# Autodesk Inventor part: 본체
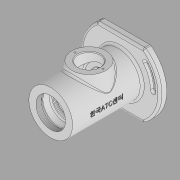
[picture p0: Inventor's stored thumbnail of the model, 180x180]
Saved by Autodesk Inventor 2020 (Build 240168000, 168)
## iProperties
Created: 2022-05
Part Number: 본체
Material: 일반
Document SubType Name: Modeling
Designer: User
Density: 1 g/cm^3
Appearance: 기본값
Mass: 256.279 g
Surface Area: 622.612 cm^2
Volume: 256.279 cm^3
Author: User
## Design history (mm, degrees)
sketch "스케치1"
  geometry: L1 (57.5, 0)-(-57.5, 0); L2 (-57.5, 0)-(-57.5, 32); L3 (44.5, 32)-(44.5, 58); L4 (44.5, 58)-(54.5, 58); L5 (54.5, 58)-(54.5, 36); L6 (54.5, 36)-(57.5, 36); L7 (57.5, 36)-(57.5, 0); L8 (-49.5, 0)-(-49.5, 24); L9 (-49.5, 24)-(-46.5, 24); L10 (-46.5, 24)-(-46.5, 22.5); L11 (-46.5, 22.5)-(-35.5, 22.5); L12 (-35.5, 22.5)-(-35.5, 17.5); L13 (-35.5, 17.5)-(-33.25, 17.5); L14 (-33.25, 17.5)-(-33.25, 18.5); L15 (-33.25, 18.5)-(-31.5, 18.5); L16 (-31.5, 18.5)-(-31.5, 17.5); L17 (-31.5, 17.5)-(-20.5, 17.5); L18 (-20.5, 17.5)-(-20.5, 27); L19 (-20.5, 27)-(17.5, 27); L20 (17.5, 27)-(17.5, 17.5); L21 (17.5, 17.5)-(28.5, 17.5); L22 (28.5, 17.5)-(28.5, 15); L23 (28.5, 15)-(33.5, 15); L24 (33.5, 15)-(33.5, 11); L25 (33.5, 11)-(36.2, 11); L26 (36.2, 11)-(36.2, 15); L27 (36.2, 15)-(43.5, 15); L28 (-57.5, 32)-(44.5, 32); L29 (43.5, 15)-(43.5, 20); L30 (43.5, 20)-(57.5, 30); 2 further points
  constraints: 60 end point, 20 perpendicular, 6 point on line, 3 vertical, 2 coincident, 2 horizontal, 1 midpoint
  dimensions: "d1" = 115 distance between parallel lines of L7 L2; "d2" = 13 distance between parallel lines of L7 L3; "d4" = 3 distance between parallel lines of L7 L5; "d5" = 116 diameter of L4 L1; "d6" = 72 diameter of L6 L1; "d7" = 64 diameter of L28 L1; "d8" = 48 diameter of L9 L1; "d9" = 45 diameter of L11 L1; "d10" = 8 distance between parallel lines of L2 L8; "d11" = 3 distance of L8.end L9.end; "d13" = 22 distance between parallel lines of L2 L12; "d14" = 14 horizontal distance of L27.end L30.end; "d17" = 29 distance between parallel lines of L22 L7; "d18" = 11 distance of L20.end L21.end; "d19" = 38 distance of L18.end L19.end; "d20" = 11 distance of L16.end L17.end; "d21" = 5 distance of L22.end L23.end; "d22" = 35 diameter of L13 L1; "d23" = 54 diameter of L19 L1; "d24" = 30 diameter of L23 L1; "d25" = 22 diameter of L25 L1; "d28" = 1.75 distance of L14.end L15.end; "d29" = 37 diameter of L15 L1; "d74" = 60 diameter of L30.end L1; "d75" = 20 vertical distance of L1.start L29.end; "d76" = 7.3 distance of L26.end L27.end; "d77" = 30 diameter of L27 L1
revolve "회전1" sketch "스케치1" stored, may be unused: angle "d30" = 90 deg
sketch "스케치2"
  geometry: C1 r 32 at (0, 0) reference; 2 further points
  constraints: 1 coincident
hole "구멍1" sketch "스케치2" at (0, 0) diameter "d31" = 43.376; stored, may be unused: countersink angle "d35" = 90 deg, drill point angle "d37" = 0 deg; dims "d32" = 8, "d33" = 4, "d34" = 2, "d36" = 8
sketch "스케치3"
  geometry: L1 (-47, -60)-(47, -60); L2 (47, -60)-(47, 60); L3 (47, 60)-(-47, 60); L4 (-47, 60)-(-47, -60); L5 (-47, -60)-(47, 60); L6 (47, -60)-(-47, 60); C1 r 58 at (0, 0) reference; 5 further points
  constraints: 12 end point, 2 midpoint, 2 parallel, 1 horizontal, 1 perpendicular
  dimensions: "d40" = 94 distance of L3.end L2.end; "d41" = 120 distance of L2.end L1.end
extrude "돌출1" cut sketch "스케치3" distance "d42" = 10; taper "d43" = 0 deg
sketch "스케치4"
  geometry: L1 (-47, 33.985)-(-47, 81.985); L2 (-47, 33.985)-(-77.854, 70.755); C1 r 32 at (-47, 33.985) reference; A1 r 48 centre (-47, 33.985) between (-47, 81.985) and (-77.854, 70.755); A2 r 4 centre (-77.854, 70.755) between (-80.425, 73.82) and (-78.806, 66.87); A3 r 4 centre (-47, 81.985) between (-47, 77.985) and (-47, 85.985); A4 r 44 centre (-47, 33.985) between (-47, 77.985) and (-75.283, 67.691); A5 r 52 centre (-47, 33.985) between (-47, 85.985) and (-80.425, 73.82); A6 r 45.75 centre (-47, 33.985) between (-47, 79.735) and (-78.806, 66.87); A7 r 50.25 centre (-47, 33.985) between (-47, 84.235) and (-81.818, 70.218); A8 r 2.25 centre (-47, 81.985) between (-47, 79.735) and (-47, 84.235); 4 further points
  constraints: 17 point on circle, 8 centre point, 6 coincident, 4 end point, 3 point on line, 1 tangent, 1 vertical
  dimensions: "d44" = 96 diameter of A1; "d45" = 40 deg angle of L2 L1; "d46" = 8 diameter of A2; "d47" = 8 diameter of A3; "d48" = 2.25 radial gap between concentric circles of A1 A6; "d49" = 2.25 radial gap between concentric circles of A1 A7
extrude "돌출2" cut sketch "스케치4" extent not by distance; stored distance "d50" = 0; taper "d51" = 0 deg
extrude "돌출3" cut sketch "스케치4" distance "d52" = 4.4; taper "d53" = 0 deg
extrude "돌출4" cut sketch "스케치4" extent not by distance; stored distance "d54" = 0; taper "d55" = 0 deg
node "작업 평면1"
chamfer "모따기2" distance "d78" = 0.7; stored, may be unused: second distance "d79" = 2, angle "d80" = 30 deg
sketch "스케치7"
  geometry: L1 (-57.5, -32)-(-57.5, 32) reference; C1 r 25 at (-1.5, 0); 1 further point
  constraints: 1 centre point, 1 horizontal alignment
  dimensions: "d83" = 50 diameter of C1; "d84" = 56 distance from line of C1.centre L1
extrude "돌출6" join sketch "스케치7" stored distance "d85" = 10; taper "d86" = 10 deg
sketch "스케치8"
  geometry: C1 r 25 at (0, 0) reference; C2 r 16 at (0, 0); 1 further point
  constraints: 1 centre point, 1 coincident
  dimensions: "d87" = 32 diameter of C2
extrude "돌출7" cut sketch "스케치8" distance "d88" = 25; taper "d89" = 0 deg
chamfer "모따기3" distance "d90" = 1; stored, may be unused: second distance "d91" = 2, angle "d92" = 30 deg
fillet "모깎기1" dims "d93" = 2
chamfer "모따기4" distance "d95" = 1; stored, may be unused: second distance "d96" = 2, angle "d97" = 30 deg
fillet "모깎기3" dims "d98" = 0.5
fillet "모깎기4" dims "d99" = 0.6
fillet "모깎기5" dims "d100" = 3
sketch "스케치9"
  geometry: L1 (0, 0)-(0, -20.5); C1 r 25 at (0, 0) reference; 2 further points
  constraints: 2 end point, 1 coincident, 1 vertical
  dimensions: "d102" = 20.5 distance of L1.start L1.end
hole "구멍3" sketch "스케치9" at (0, -20.5) diameter "d103" = 2.459; stored, may be unused: countersink angle "d107" = 90 deg, drill point angle "d109" = 118 deg; dims "d104" = 6, "d105" = 4, "d106" = 2, "d108" = 8
node "작업 평면2"
sketch "스케치10"
  geometry: L1 (41.299, -14.637)-(-39.299, -14.637); L2 (-39.299, -14.637)-(-39.299, 14.637); L3 (-39.299, 14.637)-(41.299, 14.637); L4 (41.299, 14.637)-(41.299, -14.637); L5 (41.299, -14.637)-(-39.299, 14.637); L6 (41.299, 14.637)-(-39.299, -14.637); L7 (-61, 47)-(-61, -47) reference; 3 further points
  constraints: 4 end point, 2 midpoint, 1 horizontal alignment, 2 other
  dimensions: "d113" = 62 distance from line of point (1, 0) L7
feature "엠보싱1" sketch "스케치10" dims "d1" = 115, "d2" = 13, "d4" = 3, "d5" = 116, "d6" = 72, "d7" = 64, "d8" = 48, "d9" = 45, "d10" = 8, "d11" = 3, "d13" = 22, "d14" = 14, "d17" = 29, "d18" = 11, "d19" = 38, "d20" = 11, "d21" = 5, "d22" = 35, "d23" = 54, "d24" = 30, "d25" = 22, "d28" = 1.75, "d29" = 37, "d74" = 60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
fillet "모깎기6" dims "d116" = 3
fillet "모깎기7" dims "d117" = 3
fillet "모깎기8" dims "d118" = 3
fillet "모깎기9" dims "d119" = 3
chamfer "모따기5" distance "d120" = 1; stored, may be unused: second distance "d121" = 2, angle "d122" = 30 deg
node "솔리드1"
pattern_circular "원형 패턴1" dims angle "d57" = 360 deg
pattern_circular "원형 패턴2" dims angle "d111" = 360 deg
node "투영된 루프1"
feature "A9D066F2-1C7D-4E18-AEED-F7BC21143FA4" dims "d103" = 2.459, "d104" = 6, "d105" = 4, "d106" = 2, "d107" = 90 deg, "d108" = 8, "d109" = 118 deg
other parameters: "d59" = -38
